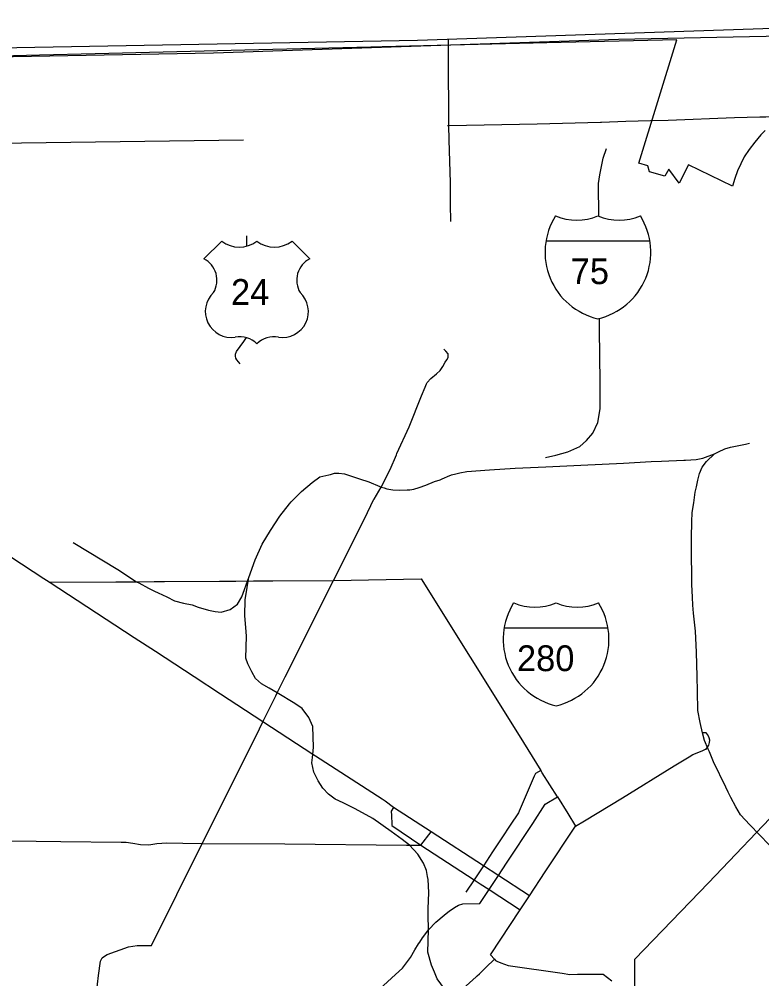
# Model space of a CAD drawing. Extents: x -232 to 448, y 619 to 1059.
# Drawn here: x 157.16 to 183.77, y 925.75 to 960.13 of the extents above; entities that cross this region are included whole.
import ezdxf

# ---------------------------------------------------------------- set-up
doc = ezdxf.new("R2010")
doc.units = 0
doc.layers.add('Default', color=7, linetype='Continuous')

msp = doc.modelspace()

# ---------------------------------------------------------------- linework, layer by layer
at = {"layer": 'Default'}
for p, q in [((164.414, 952.179), (163.78, 951.545)), ((164.414, 952.179), (163.78, 951.545)), ((167.569, 951.545), (166.935, 952.179)), ((167.569, 951.545), (166.935, 952.179)), ((176.034, 952.19), (179.754, 952.19)), ((174.534, 938.326), (178.254, 938.326))]:
    msp.add_line(p, q, dxfattribs=at)
for points in [[(145.054, 958.769), (150.927, 958.948), (156.407, 959.102), (171.427, 959.378), (185.934, 959.863), (198.796, 960.129)], [(191.559, 959.664), (178.631, 959.398), (164.124, 958.912), (149.104, 958.636), (143.624, 958.482), (132.12, 958.132), (126.614, 958.11), (126.592, 958.099), (122.234, 957.803), (110.103, 957.439)], [(170.161, 959.137), (169.752, 959.127), (165.246, 959.016)], [(176.062, 959.283), (170.161, 959.137)], [(172.546, 958.654), (172.543, 959.415)], [(180.725, 959.39), (176.062, 959.283)], [(179.362, 954.97), (180.725, 959.39)], [(159.881, 958.884), (157.886, 958.834), (154.62, 958.754)], [(165.246, 959.016), (159.881, 958.884)], [(172.554, 956.536), (172.546, 958.654)], [(172.501, 956.318), (172.555, 956.319), (175.722, 956.381)], [(172.555, 956.319), (172.554, 956.536)], [(175.722, 956.381), (177.982, 956.443), (178.021, 956.445)], [(178.021, 956.445), (178.898, 956.47)], [(178.898, 956.47), (179.774, 956.494)], [(179.774, 956.494), (180.415, 956.513), (182.791, 956.601), (183.699, 956.631), (183.914, 956.633), (184.029, 956.638), (184.179, 956.603), (184.421, 956.528), (184.616, 956.438)], [(172.568, 955.812), (172.555, 956.319)], [(183.888, 956.147), (183.725, 955.981), (183.51, 955.722), (183.31, 955.459), (183.135, 955.195), (183.01, 954.951), (182.89, 954.701), (182.803, 954.419), (182.71, 954.152)], [(151.4, 955.706), (154.583, 955.662), (165.199, 955.801)], [(172.62, 952.884), (172.623, 953.053), (172.616, 953.33), (172.617, 953.634), (172.61, 953.957), (172.609, 954.261), (172.568, 955.812)], [(177.932, 953.066), (177.915, 954.247), (177.958, 954.556), (178.078, 955.149), (178.204, 955.495)], [(179.682, 954.881), (179.362, 954.97)], [(182.71, 954.152), (181.141, 954.907), (180.801, 954.258), (180.439, 954.758), (180.295, 954.5), (179.739, 954.66), (179.682, 954.881)], [(165.312, 951.997), (165.318, 952.367)], [(176.019, 944.425), (176.386, 944.506), (176.818, 944.627), (177.246, 944.823), (177.489, 945.037), (177.71, 945.302), (177.89, 945.676), (177.975, 946.172), (177.972, 947.123), (177.95, 949.009), (177.955, 949.413)], [(165.073, 947.788), (165.011, 947.85), (164.959, 947.927), (164.921, 947.989), (164.908, 948.061), (164.909, 948.134), (164.946, 948.22), (165.212, 948.584), (165.297, 948.723)], [(171.75, 947.064), (171.771, 947.119), (171.913, 947.255), (172.11, 947.429), (172.237, 947.549), (172.332, 947.686), (172.422, 947.837), (172.475, 947.93), (172.527, 948.008), (172.524, 948.084), (172.523, 948.142), (172.446, 948.231), (172.374, 948.305)], [(170.694, 944.569), (171.128, 945.526), (171.577, 946.641), (171.705, 946.943), (171.75, 947.064)], [(182.074, 944.556), (182.216, 944.63), (182.445, 944.732), (182.64, 944.796), (183.176, 944.91), (183.32, 944.942)], [(170.127, 943.368), (170.449, 944.002), (170.674, 944.526), (170.694, 944.569)], [(181.027, 944.333), (181.411, 944.357), (181.658, 944.4), (182.074, 944.556)], [(181.645, 934.56), (181.553, 934.932), (181.478, 935.362), (181.459, 936.053), (181.452, 936.577), (181.42, 937.459), (181.388, 938.2), (181.319, 938.854), (181.3, 939.141), (181.278, 939.428), (181.261, 939.882), (181.258, 940.181), (181.241, 940.955), (181.25, 941.566), (181.254, 942.117), (181.276, 942.455), (181.336, 942.805), (181.374, 943.186), (181.425, 943.371), (181.474, 943.618), (181.532, 943.857), (181.633, 944.081), (181.785, 944.285), (182.074, 944.556)], [(172.318, 943.664), (172.393, 943.696), (172.506, 943.746), (172.653, 943.804), (172.797, 943.843), (172.948, 943.872), (173.191, 943.92), (174.012, 943.983), (174.923, 944.042), (176.023, 944.092), (177.278, 944.149), (178.812, 944.228), (179.801, 944.288), (180.167, 944.301)], [(180.167, 944.301), (180.967, 944.329), (181.027, 944.333)], [(166.904, 942.835), (167.27, 943.21), (167.654, 943.528), (167.936, 943.73), (168.257, 943.803)], [(168.257, 943.803), (168.311, 943.819)], [(168.311, 943.819), (168.451, 943.861), (168.614, 943.871), (168.813, 943.838), (169.355, 943.666), (169.686, 943.556), (170.075, 943.39)], [(171.157, 943.266), (171.294, 943.289), (171.486, 943.351), (171.733, 943.434), (172.039, 943.563), (172.244, 943.632), (172.318, 943.664)], [(169.87, 942.934), (169.873, 942.939), (170.127, 943.368)], [(170.075, 943.39), (170.127, 943.368), (170.232, 943.338)], [(170.232, 943.338), (170.336, 943.309), (170.541, 943.265), (170.773, 943.251), (171.059, 943.264), (171.157, 943.266)], [(158.045, 940.085), (154.06, 942.684)], [(165.391, 940.125), (165.608, 940.756), (165.864, 941.32), (166.16, 941.816), (166.501, 942.325), (166.839, 942.769), (166.904, 942.835)], [(168.421, 940.024), (169.528, 942.232), (169.87, 942.934)], [(159.094, 941.377), (160.692, 940.416), (161.36, 939.978), (161.446, 939.932)], [(158.228, 939.966), (158.045, 940.085)], [(158.228, 939.966), (160.62, 939.975)], [(161.276, 937.972), (158.228, 939.966)], [(160.62, 939.975), (161.36, 939.978), (161.997, 939.982)], [(161.446, 939.932), (161.79, 939.745), (162.011, 939.639)], [(161.997, 939.982), (162.369, 939.985)], [(162.369, 939.985), (164.333, 939.998)], [(164.184, 938.904), (164.4, 938.884), (164.715, 938.981), (164.985, 939.173), (165.138, 939.43), (165.391, 940.125)], [(164.333, 939.998), (164.917, 940.001)], [(164.917, 940.001), (165.554, 940.005)], [(165.33, 939.77), (165.391, 940.125)], [(165.554, 940.005), (166.032, 940.009)], [(166.032, 940.009), (166.244, 940.01)], [(166.244, 940.01), (168.421, 940.024), (171.559, 940.084)], [(166.689, 936.568), (168.421, 940.024)], [(171.559, 940.084), (175.067, 934.469)], [(162.011, 939.639), (162.139, 939.578), (162.452, 939.43), (162.727, 939.297), (163.048, 939.205), (163.36, 939.144), (163.575, 939.071), (163.937, 938.953), (164.184, 938.904)], [(165.291, 938.177), (165.24, 938.771), (165.254, 939.328), (165.33, 939.77)], [(166.401, 935.992), (166.111, 936.162), (165.846, 936.321), (165.623, 936.507), (165.492, 936.751), (165.352, 937.039), (165.283, 937.237), (165.303, 938.032), (165.291, 938.177)], [(162.038, 937.474), (161.276, 937.972)], [(163.427, 936.565), (162.038, 937.474)], [(164.369, 935.949), (163.427, 936.565)], [(166.352, 935.893), (166.401, 935.992), (166.689, 936.568)], [(165.265, 935.362), (164.369, 935.949)], [(165.892, 934.952), (166.352, 935.893)], [(167.669, 933.684), (167.683, 933.785), (167.705, 934.046), (167.689, 934.416), (167.677, 934.79), (167.54, 935.114), (167.295, 935.438), (167.03, 935.616), (166.401, 935.992)], [(165.892, 934.952), (165.265, 935.362)], [(165.77, 934.707), (165.892, 934.952)], [(167.775, 933.726), (167.683, 933.785), (165.892, 934.952)], [(165.575, 934.316), (165.77, 934.707)], [(175.067, 934.469), (175.849, 933.217)], [(181.754, 933.973), (181.773, 933.981), (181.865, 934.12), (181.891, 934.218), (181.899, 934.303), (181.879, 934.385), (181.829, 934.49), (181.766, 934.565), (181.645, 934.56)], [(181.848, 933.979), (181.712, 934.287), (181.645, 934.56)], [(163.72, 930.599), (165.575, 934.316)], [(167.834, 932.911), (167.712, 933.151), (167.642, 933.487), (167.669, 933.684)], [(170.265, 932.117), (170.168, 932.19), (167.775, 933.726)], [(180.627, 933.376), (181.162, 933.703), (181.296, 933.782), (181.625, 933.92), (181.704, 933.953)], [(181.704, 933.953), (181.754, 933.973)], [(181.889, 933.885), (181.848, 933.979)], [(182.565, 932.44), (182.479, 932.616), (182.033, 933.524), (181.918, 933.818), (181.889, 933.885)], [(178.77, 932.239), (180.627, 933.376)], [(175.614, 933.012), (175.074, 931.76)], [(175.849, 933.217), (175.653, 933.102), (175.614, 933.012)], [(175.901, 933.134), (175.849, 933.217)], [(176.443, 932.27), (175.901, 933.134)], [(170.881, 930.739), (170.49, 931.029), (169.829, 931.497), (169.197, 931.836), (169.054, 931.918), (168.772, 932.053), (168.482, 932.184), (168.242, 932.366), (168.033, 932.578), (167.868, 932.843), (167.834, 932.911)], [(186.508, 926.272), (186.361, 926.448), (186.209, 926.787), (186.101, 927.107), (185.985, 927.525), (185.767, 928.027), (185.49, 928.431), (185.184, 928.932), (184.664, 929.891), (184.031, 930.55), (183.337, 931.269), (183.003, 931.627), (182.833, 931.915), (182.658, 932.251), (182.565, 932.44)], [(170.573, 931.885), (170.265, 932.117)], [(175.557, 931.32), (176.009, 932.006), (176.443, 932.27)], [(176.443, 932.27), (176.811, 931.673)], [(177.41, 931.408), (178.77, 932.239)], [(179.21, 923.676), (179.218, 926.456), (181.854, 929.191), (184.545, 932.004)], [(170.573, 931.885), (170.487, 931.752), (170.493, 931.596), (170.509, 931.288)], [(171.924, 931.015), (170.573, 931.885)], [(175.074, 931.76), (175.048, 931.699), (174.753, 931.254)], [(176.811, 931.673), (177.093, 931.214)], [(170.509, 931.288), (170.512, 931.242), (171.552, 930.543)], [(174.641, 929.93), (175.557, 931.32)], [(177.093, 931.214), (177.41, 931.408)], [(171.552, 930.543), (171.924, 931.015)], [(173.789, 929.797), (171.924, 931.015)], [(174.753, 931.254), (174.452, 930.798)], [(176.009, 929.587), (177.093, 931.214)], [(155.998, 930.705), (158.647, 930.675)], [(158.647, 930.675), (160.81, 930.649)], [(160.81, 930.649), (160.994, 930.647), (161.227, 930.607), (161.51, 930.563), (161.804, 930.557), (162.096, 930.599), (162.451, 930.623), (163.018, 930.612)], [(161.896, 926.941), (163.72, 930.599)], [(163.018, 930.612), (163.72, 930.599), (166.671, 930.581), (171.034, 930.544)], [(171.788, 929.422), (171.756, 929.636), (171.643, 929.896), (171.437, 930.221), (171.144, 930.544), (170.881, 930.739)], [(174.452, 930.798), (174.121, 930.298)], [(171.034, 930.544), (171.144, 930.544), (171.552, 930.543)], [(171.552, 930.543), (173.457, 929.3)], [(174.121, 930.298), (173.789, 929.797)], [(174.306, 929.421), (174.641, 929.93)], [(173.789, 929.797), (173.457, 929.3)], [(174.307, 929.462), (173.789, 929.797)], [(175.437, 928.729), (176.009, 929.587)], [(171.817, 927.887), (171.809, 928.262), (171.839, 928.839), (171.806, 929.306), (171.788, 929.422)], [(173.457, 929.3), (173.16, 928.86)], [(173.457, 929.3), (173.672, 929.159)], [(173.97, 928.912), (173.994, 928.948), (174.306, 929.421)], [(175.437, 928.729), (174.307, 929.462)], [(173.66, 928.455), (173.97, 928.912)], [(173.672, 929.159), (173.994, 928.948)], [(173.994, 928.948), (175.111, 928.221)], [(175.111, 928.221), (175.437, 928.729)], [(172.459, 928.092), (172.562, 928.179), (172.754, 928.312), (172.895, 928.386), (173.058, 928.442), (173.66, 928.455)], [(174.047, 926.606), (175.111, 928.221)], [(171.606, 927.218), (171.617, 927.235), (171.826, 927.501), (172.087, 927.775), (172.384, 928.029), (172.459, 928.092)], [(171.822, 927.667), (171.817, 927.887)], [(172.036, 925.989), (171.927, 926.244), (171.8, 926.706), (171.826, 927.501), (171.822, 927.667)], [(171.466, 927.001), (171.508, 927.065), (171.606, 927.218)], [(160.037, 923.334), (160.039, 923.504), (160.038, 923.897), (160.036, 924.226), (159.992, 924.516), (159.926, 925.249), (160.003, 925.871), (160.075, 926.382), (160.134, 926.504), (160.217, 926.563), (160.308, 926.617), (161.08, 926.901), (161.38, 926.945), (161.896, 926.941)], [(170.64, 925.902), (170.897, 926.138), (171.175, 926.517), (171.328, 926.792), (171.466, 927.001)], [(174.19, 926.451), (174.047, 926.606)], [(173.645, 925.934), (173.879, 926.156)], [(173.879, 926.156), (174.19, 926.451)], [(174.19, 926.451), (174.227, 926.411)], [(174.227, 926.411), (174.276, 926.388)], [(174.276, 926.388), (174.421, 926.318), (174.675, 926.224), (176.608, 925.956), (176.887, 925.903), (177.16, 925.912), (177.927, 925.92)], [(168.217, 923.684), (170.64, 925.902)], [(172.591, 925.142), (172.496, 925.265), (172.139, 925.748), (172.036, 925.989)], [(172.811, 925.176), (173.528, 925.824)], [(173.528, 925.824), (173.572, 925.864), (173.645, 925.934)], [(177.927, 925.92), (178.08, 925.921), (178.387, 925.679)]]:
    msp.add_lwpolyline(points, dxfattribs=at)
for centre, radius, start, end in [((178.444, 951.78), 2.445, 147.8216, 256.9941), ((178.444, 951.78), 2.445, 147.8216, 256.9941), ((177.135, 954.879), 1.951, 247.0848, 292.9105), ((177.135, 954.879), 1.951, 247.0848, 292.9105), ((177.344, 951.78), 2.445, 283.0065, 32.1787), ((178.654, 954.88), 1.951, 247.0916, 292.9084), ((177.344, 951.78), 2.445, 283.0065, 32.1787), ((178.654, 954.88), 1.951, 247.0916, 292.9084), ((165.044, 952.98), 1.019, 231.813, 308.187), ((165.044, 952.98), 1.019, 231.813, 308.187), ((166.304, 952.98), 1.019, 231.813, 308.187), ((166.304, 952.98), 1.019, 231.813, 308.187), ((163.383, 950.779), 0.862, 329.1175, 62.6108), ((163.383, 950.779), 0.862, 329.1175, 62.6108), ((167.965, 950.779), 0.862, 117.3892, 210.8825), ((167.965, 950.779), 0.862, 117.3892, 210.8825), ((164.757, 949.657), 0.93, 133.0046, 278.7282), ((164.757, 949.657), 0.93, 133.0046, 278.7282), ((166.591, 949.657), 0.93, 261.2718, 46.9954), ((166.591, 949.657), 0.93, 261.2718, 46.9954), ((165.07, 947.923), 0.832, 43.4177, 101.8742), ((165.07, 947.923), 0.832, 43.4177, 101.8742), ((166.296, 947.867), 0.883, 79.9613, 134.7468), ((166.296, 947.867), 0.883, 79.9613, 134.7468), ((176.944, 937.916), 2.445, 147.8216, 256.9941), ((176.944, 937.916), 2.445, 147.8216, 256.9941), ((175.635, 941.015), 1.951, 247.0848, 292.9105), ((175.635, 941.015), 1.951, 247.0848, 292.9105), ((175.844, 937.916), 2.445, 283.0065, 32.1787), ((177.154, 941.016), 1.951, 247.0916, 292.9084), ((175.844, 937.916), 2.445, 283.0065, 32.1787), ((177.154, 941.016), 1.951, 247.0916, 292.9084)]:
    msp.add_arc(centre, radius, start, end, dxfattribs=at)

# ---------------------------------------------------------------- texts
for s, p in [('75', (176.918, 950.637)), ('24', (164.747, 949.895)), ('280', (174.992, 936.773))]:
    msp.add_text(s, height=0.9234, dxfattribs=at).set_placement(p)

doc.saveas('drawing.dxf')
